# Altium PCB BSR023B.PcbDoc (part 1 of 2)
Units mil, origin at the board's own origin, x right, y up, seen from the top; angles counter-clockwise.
Board outline 3000 x 3000 mil, 4 copper layers (Top Layer, MidLayer 1, Mid Layer 2, Bottom Layer), stack 60.8 mil thick; 95 components, 24 nets, 183 pads, 215 vias.
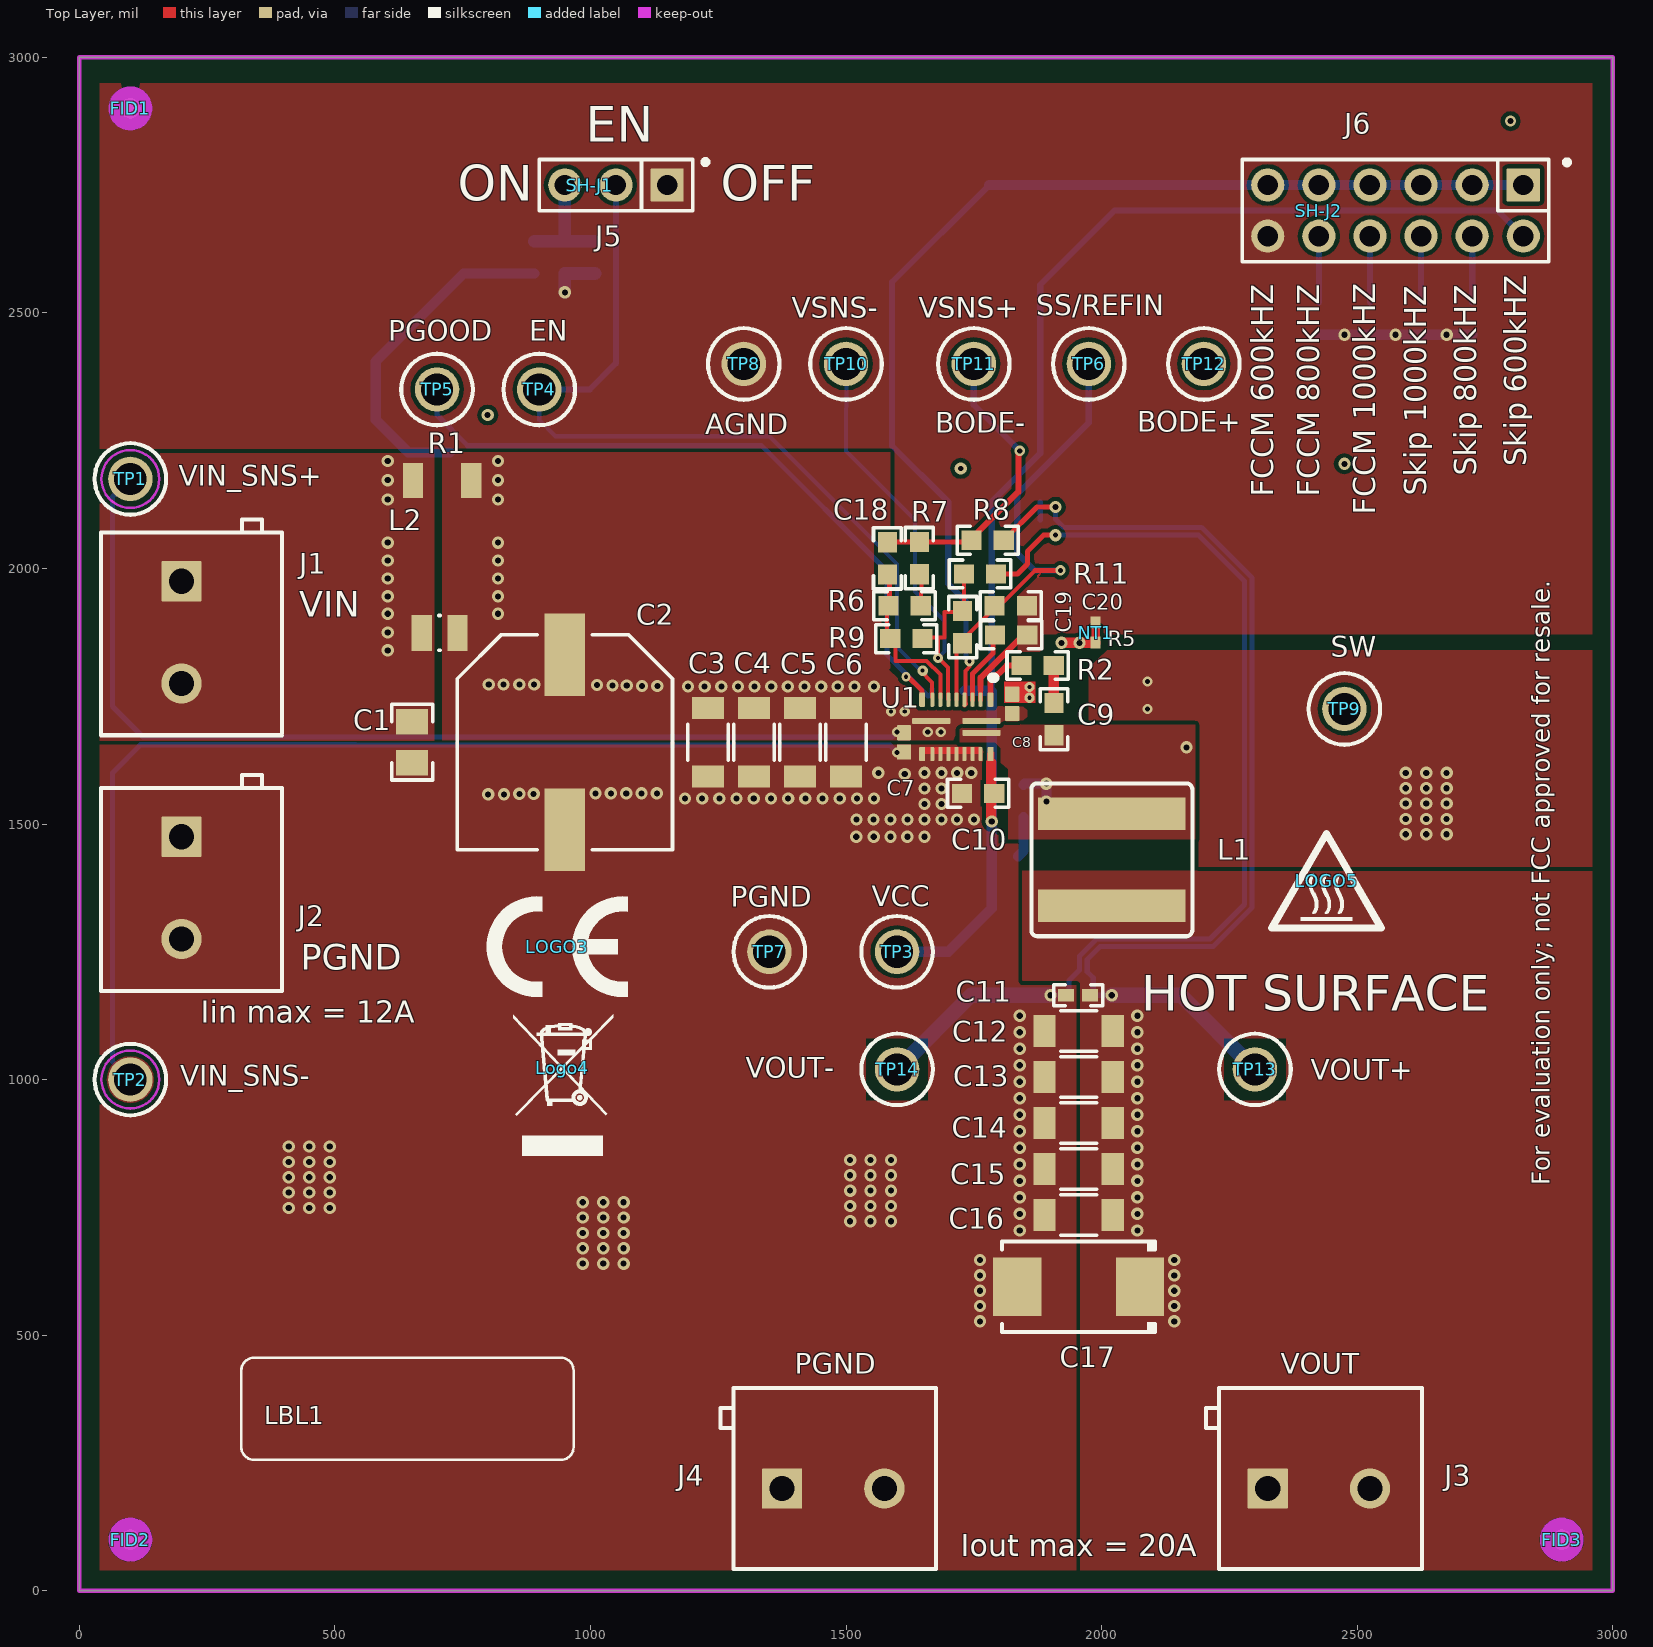
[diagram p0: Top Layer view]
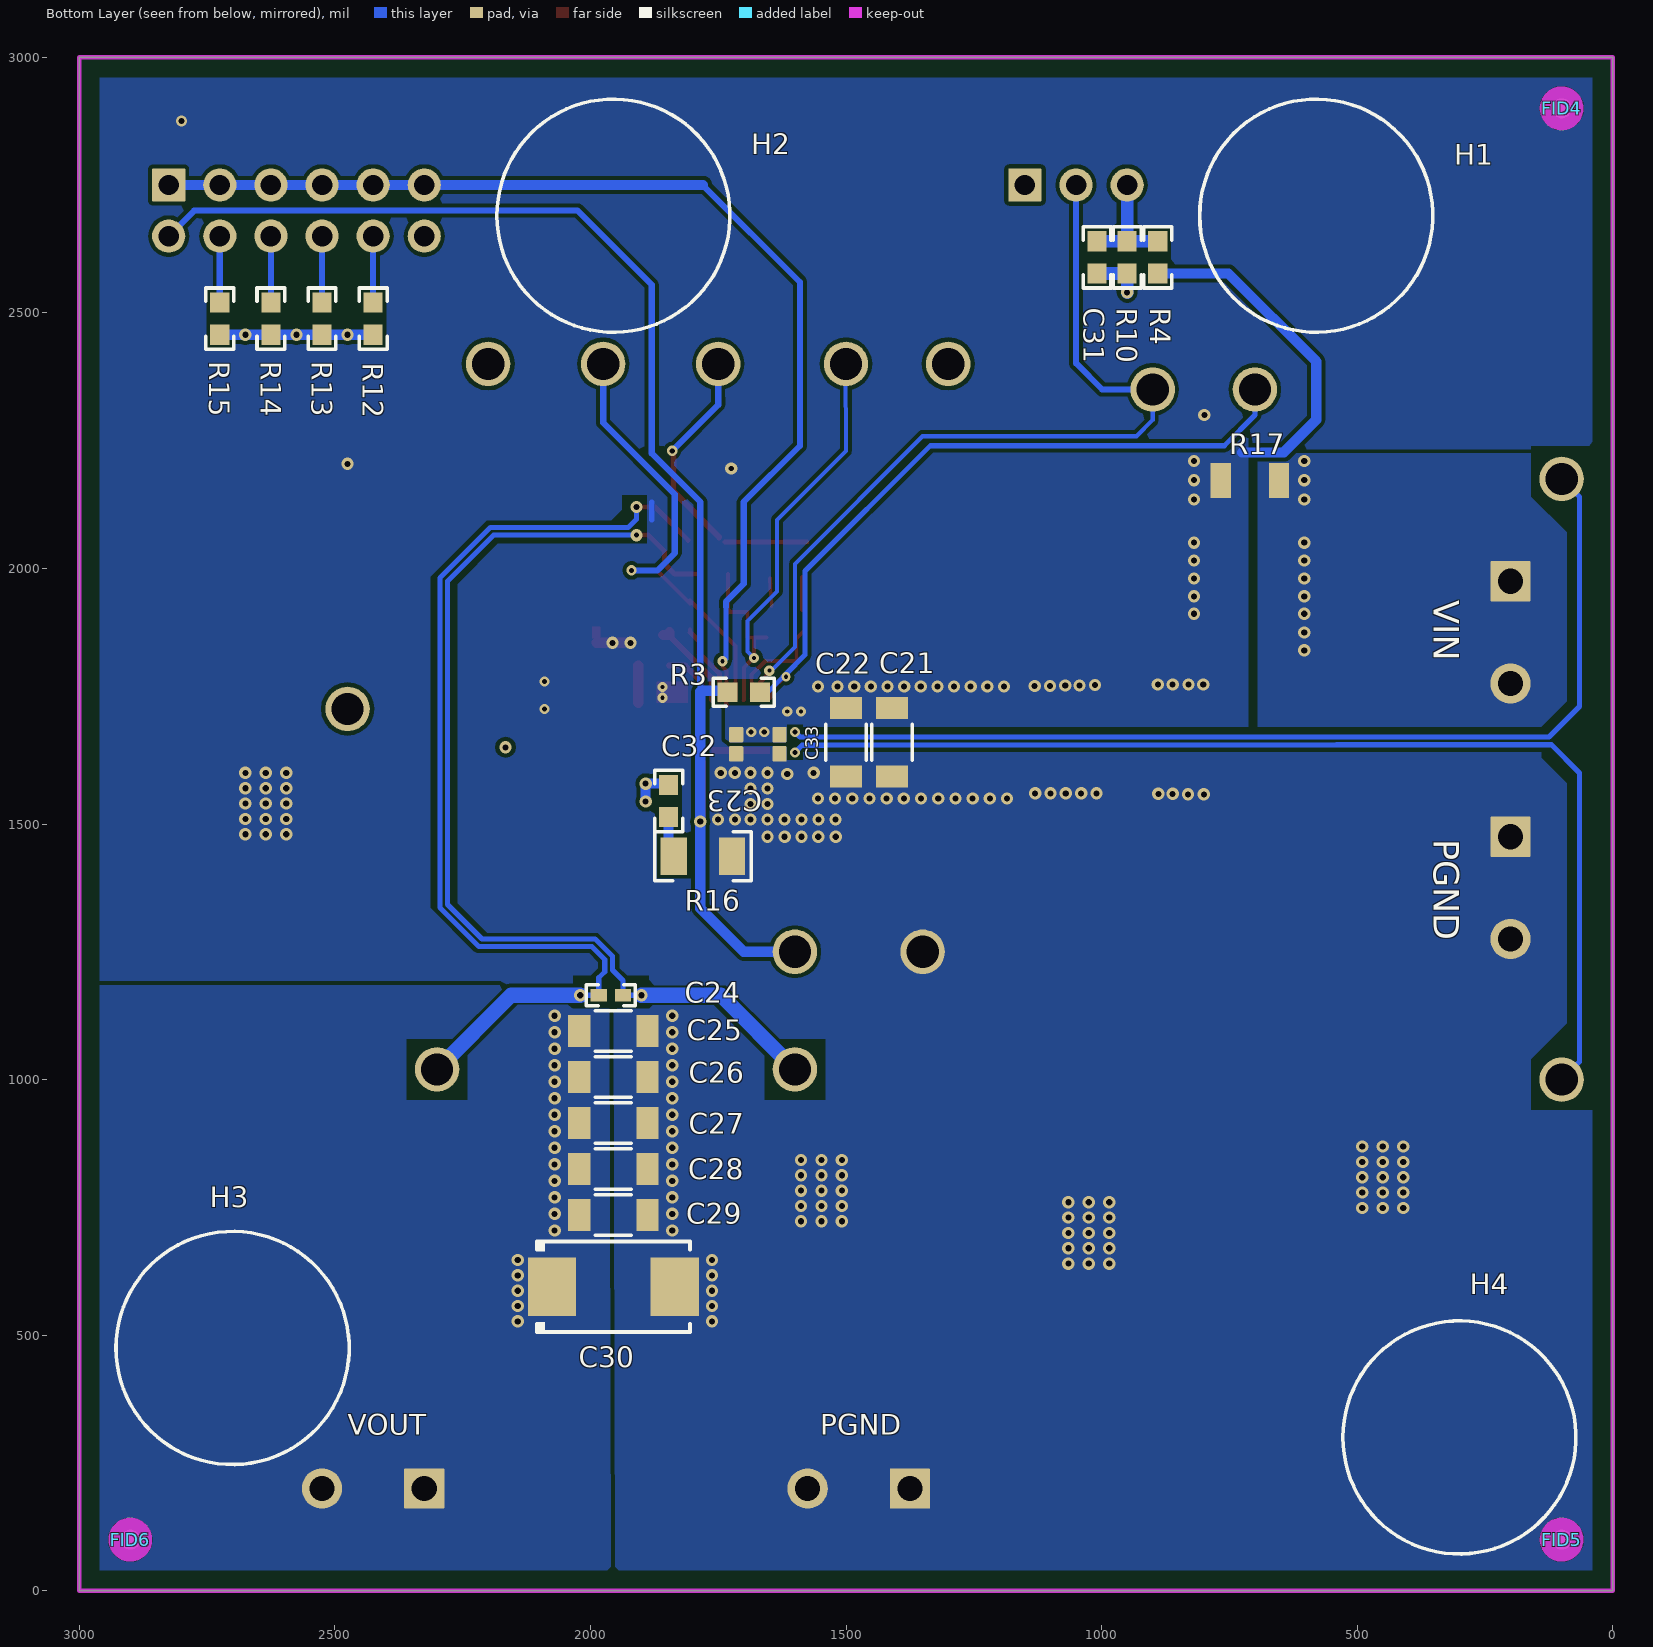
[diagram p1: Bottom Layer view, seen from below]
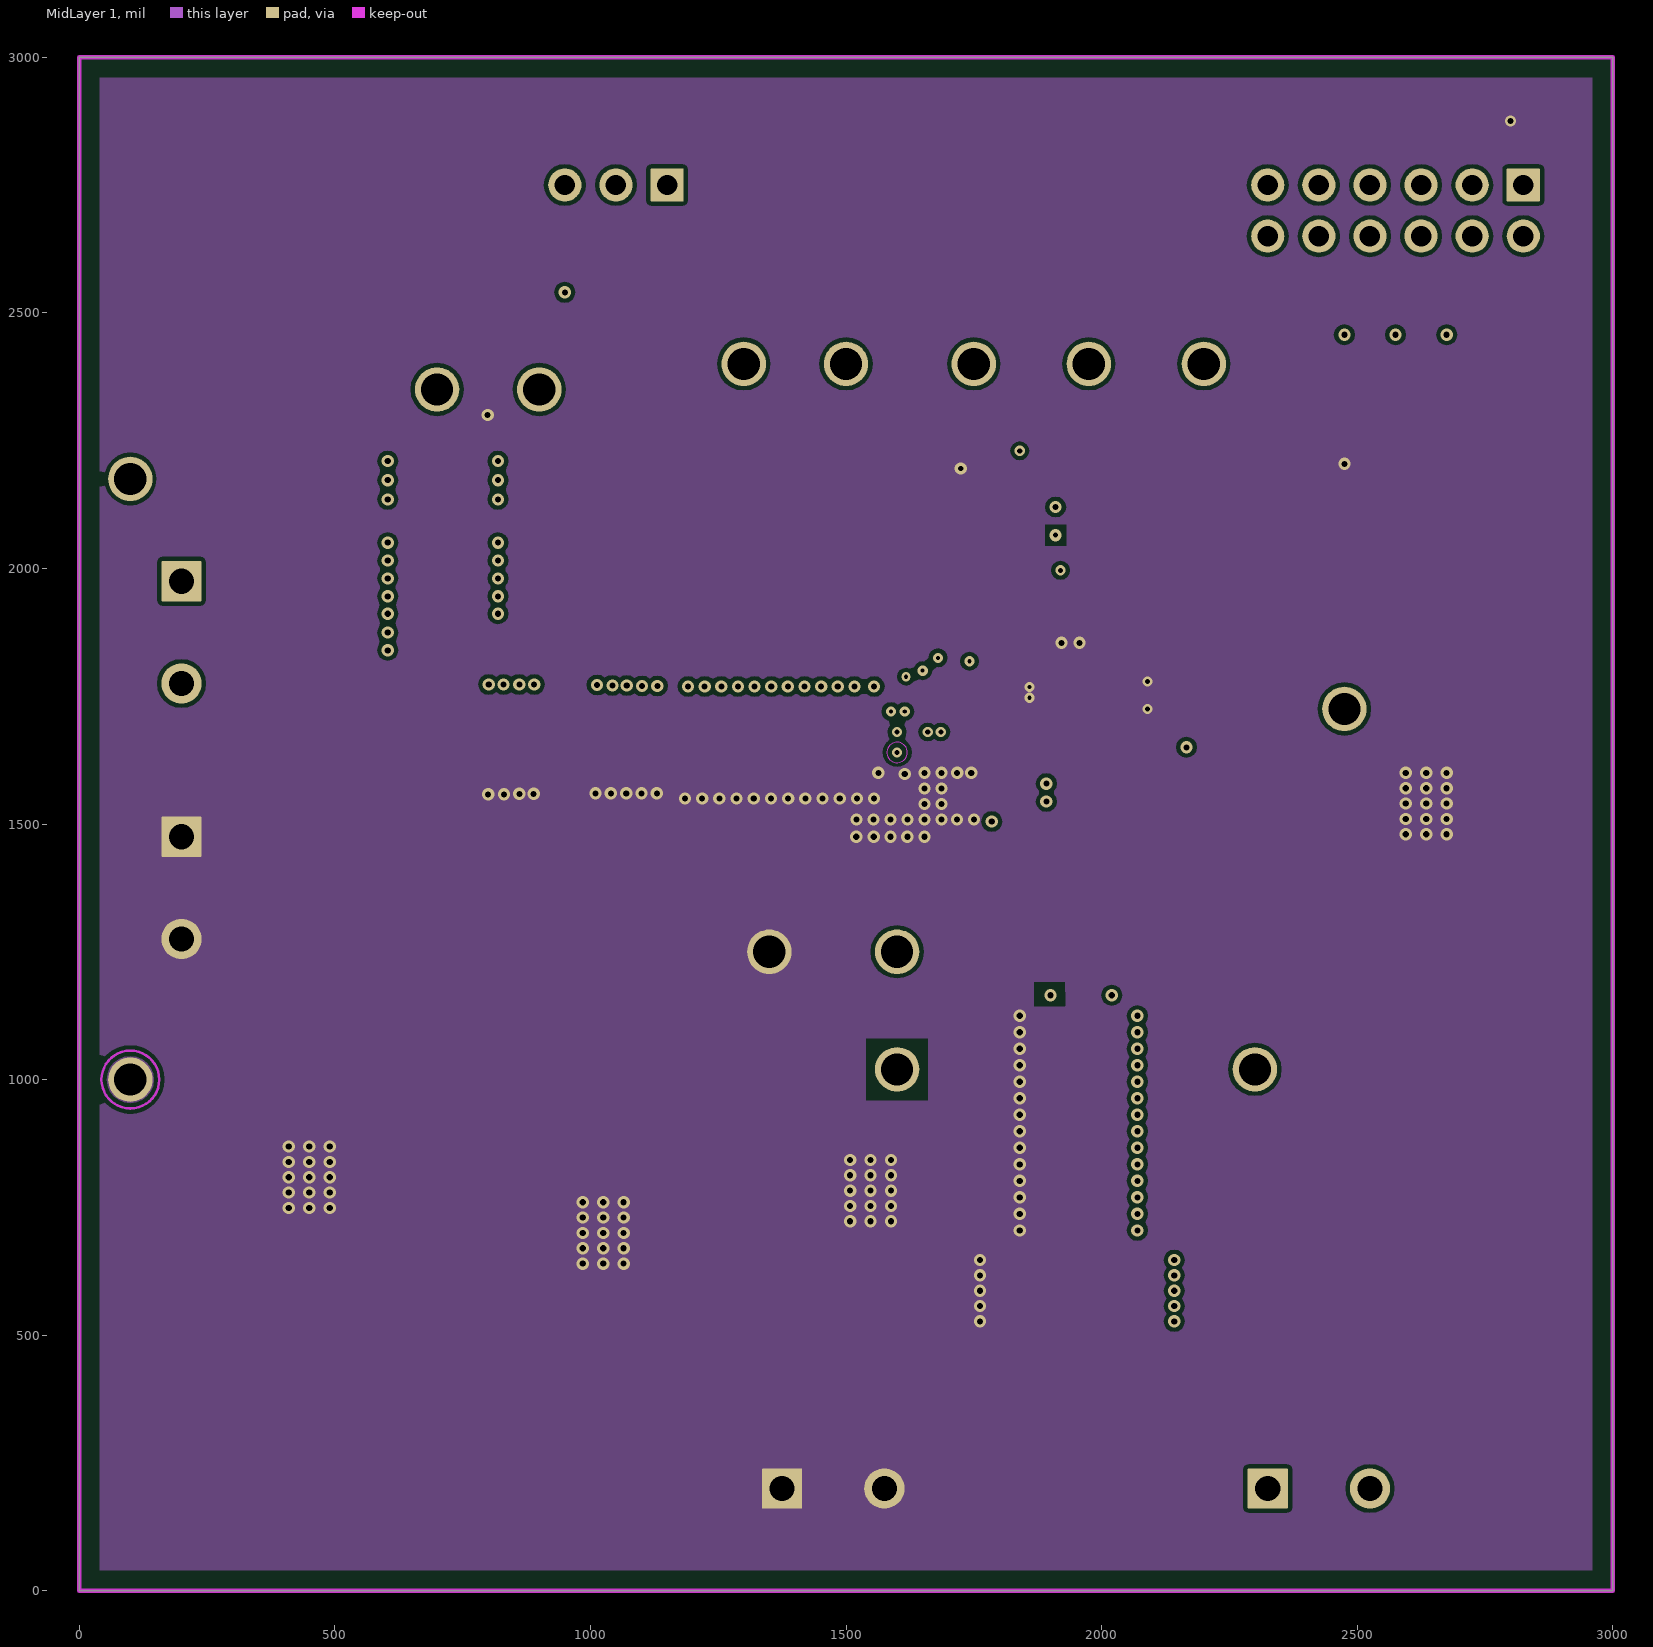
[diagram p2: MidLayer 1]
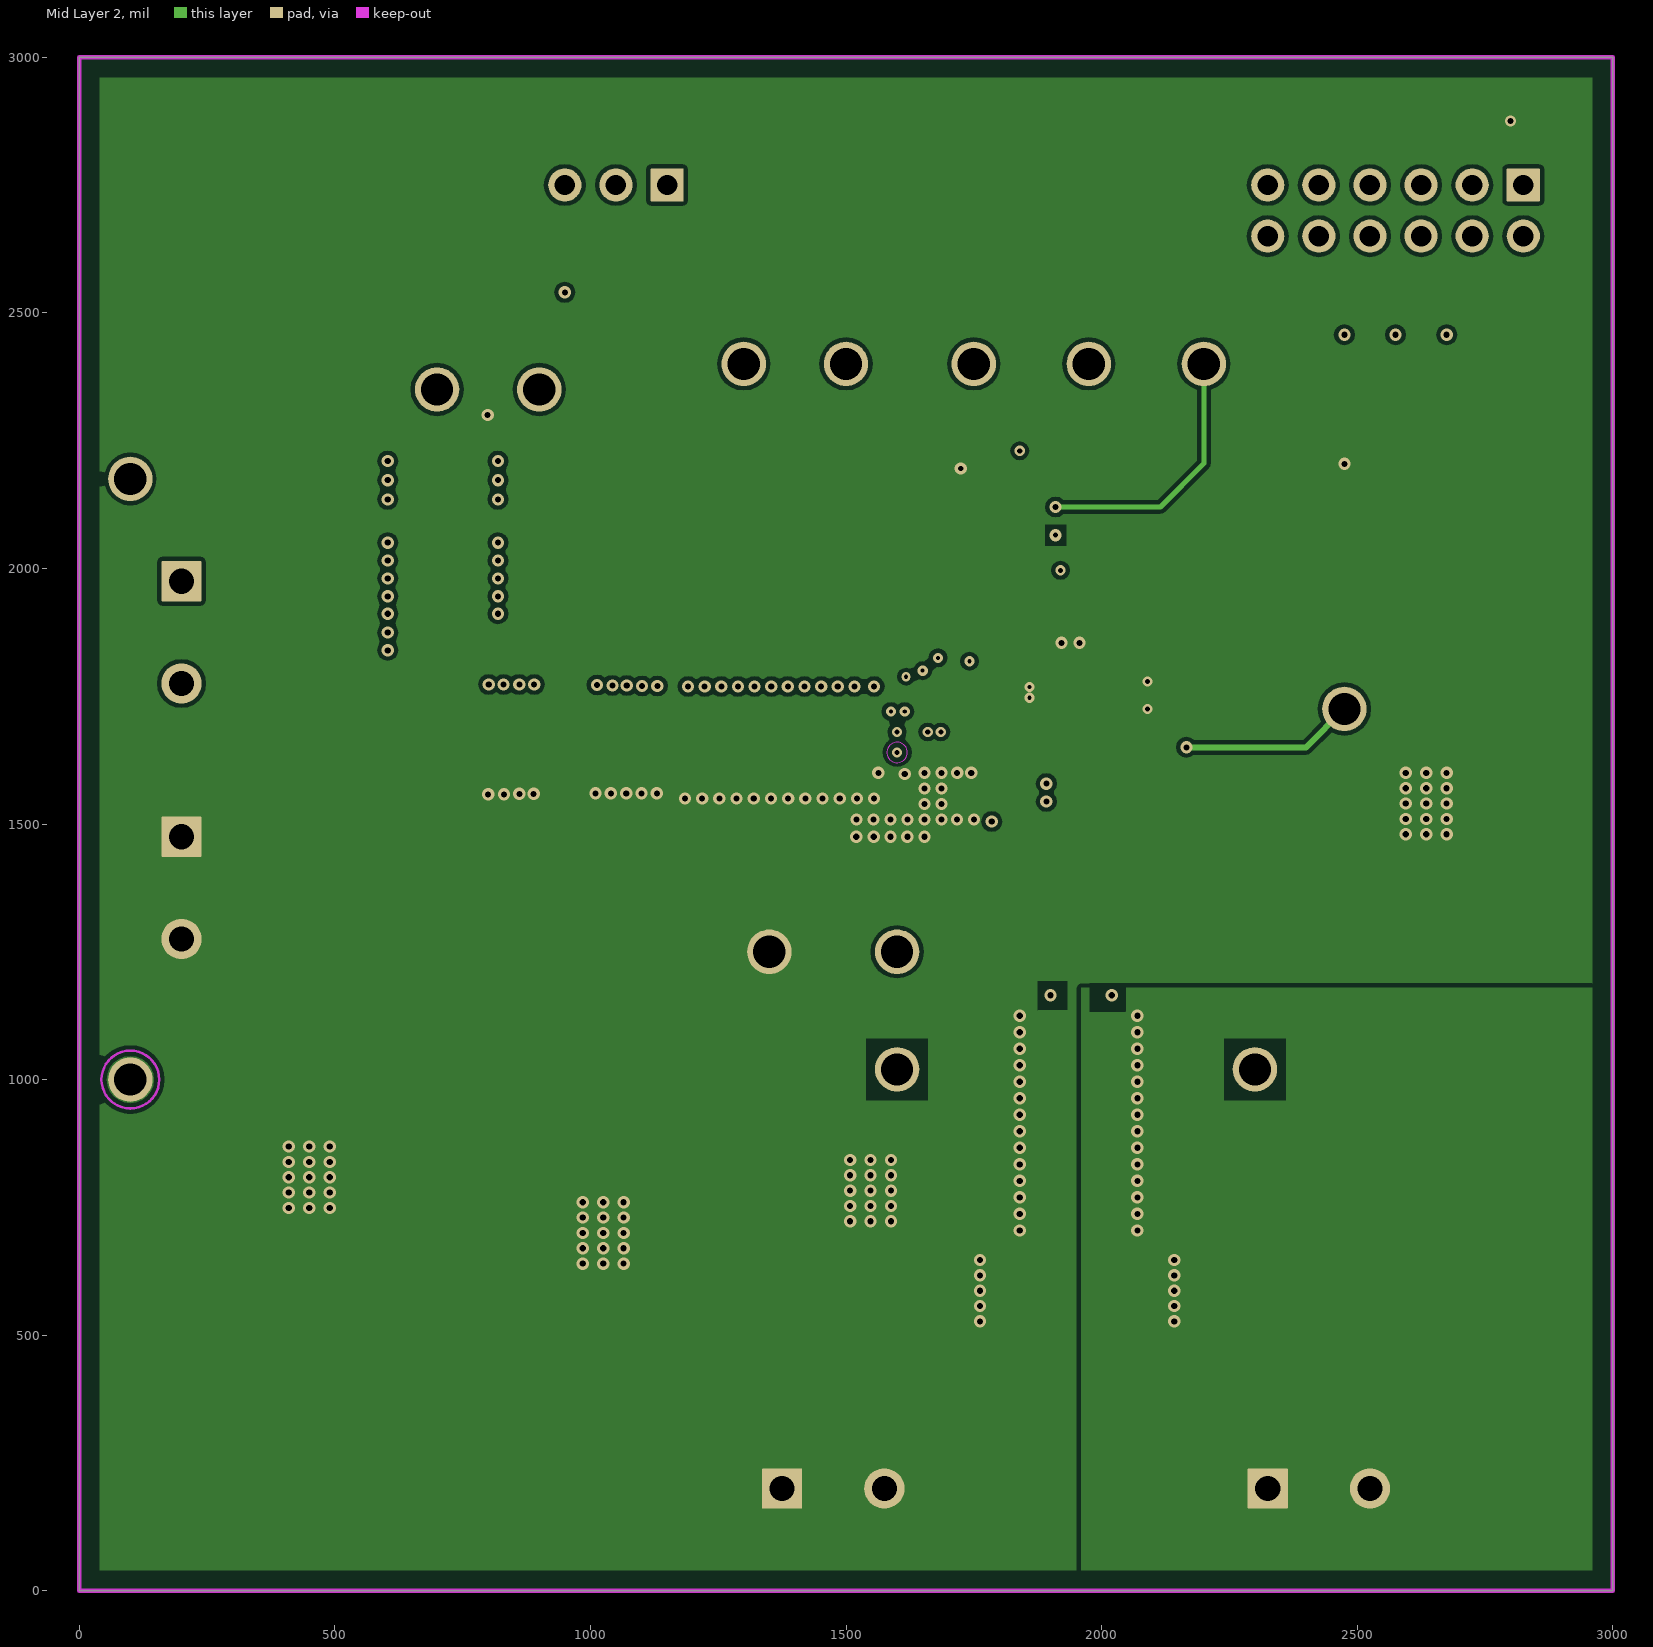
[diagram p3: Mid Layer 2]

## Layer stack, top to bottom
Top Solder: solder mask 0.4, Solder Resist, Dk 3.5
Top Layer: signal copper 2.8
Dielectric1: prepreg 9.3, FR-4 High TG, Dk 4.2
MidLayer 1: signal copper 2.8
Dielectric 2: core 31, FR-4 High TG, Dk 4.2
Mid Layer 2: signal copper 2.8
Dielectric 3: prepreg 9.3, FR-4 High TG, Dk 4.2
Bottom Layer: signal copper 2.8
Bottom Solder: solder mask 0.4, Solder Resist, Dk 3.5

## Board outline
0,0 0,3000 3000,3000 3000,0

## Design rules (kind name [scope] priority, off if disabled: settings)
AcuteAngle [All] p1: minimum=4.50000000000000E+0001 checktracksonly=FALSE
AssemblyTestPointUsage [All] p1: valid=2
BoardOutlineClearance BoardOutlineClearance_MountingHoles [OnCopper and InComponentClass('Mounting Holes')] p1: gap=40 ignorepadtopadclearanceinfootprint=FALSE
BoardOutlineClearance BoardOutlineClearance_Poly [OnCopper and InPoly] p2: gap=25 ignorepadtopadclearanceinfootprint=FALSE
BoardOutlineClearance [OnCopper and Not InComponentClass('Logo') and not InComponentClass('FiducialMark') and not InRegion(1000,500,4000,800)] p3: gap=40 ignorepadtopadclearanceinfootprint=FALSE
Clearance Clearance_Fiducial [(InComponentClass('FiducialMark') AND IsArc)] p1: gap=0 ignorepadtopadclearanceinfootprint=TRUE
Clearance Clearance_Keepouts [((IsTrack Or IsArc) And Not InPoly) And IsFree and IsKeepOut vs ((IsTrack Or IsArc) And Not InPoly) And IsFree and IsKeepOut] p2: gap=0 ignorepadtopadclearanceinfootprint=FALSE
Clearance Clearance_Poly [InPolygon] p3: gap=8 ignorepadtopadclearanceinfootprint=FALSE except(0: Arc-Hole Track-Hole SMDPad-Hole THPad-Hole Via-Hole Fill-Hole Poly-Hole Region-Hole Text-Hole)
Clearance [All] p4: gap=5 ignorepadtopadclearanceinfootprint=TRUE
ComponentClearance ComponentClearance_U1 [InComponent('U1')] p1: gap=3 collisioncheckmode=3 verticalgap=3 showdistances=FALSE
ComponentClearance ComponentClearance_MountingHoles_FiducialMarks [InComponentClass('Mounting Holes') vs InComponentClass('FiducialMark')] p2: gap=50 collisioncheckmode=3 verticalgap=8 showdistances=TRUE
ComponentClearance ComponentClearance_Shunt [InComponentClass('Header') vs InComponentClass('Shunt')] p3: gap=0 collisioncheckmode=3 verticalgap=0 showdistances=FALSE
ComponentClearance ComponentClearance_Logo [InComponentClass('Logo')] p4: gap=50 collisioncheckmode=3 verticalgap=10 showdistances=FALSE
ComponentClearance ComponentClearance_ScrewToNut [(HasFootprint('NY PMS 440 0025 PH')) vs (HasFootprint('Keystone_1902C'))] p5: gap=5 collisioncheckmode=3 verticalgap=10 showdistances=FALSE
ComponentClearance ComponentClearance_MountingHoles [InComponentClass('Mounting Holes')] p6: gap=250 collisioncheckmode=3 verticalgap=100000 showdistances=FALSE
ComponentClearance ComponentClearance_SmallPassives [HasFootprint('0201*') or HasFootprint('0402*') or HasFootprint('0508') or HasFootprint('0603*') or HasFootprint('0612') or HasFootprint('0805*') or HasFootprint('0815*') or HasFootprint('0830*') or HasFootprint('1206*') or HasFootprint('1210*') or HasFootprint('1808*') or HasFootprint('1812*') or HasFootprint('1825*') or HasFootprint('2010*') or HasFootprint('2220*') or HasFootprint('2225*') or HasFootprint('2512*') or HasFootprint('2728*') or HasFootprint('3518*') vs HasFootprint('0201*') or HasFootprint('0402*') or HasFootprint('0508') or HasFootprint('0603*') or HasFootprint('0612') or HasFootprint('0805*') or HasFootprint('0815*') or HasFootprint('0830*') or HasFootprint('1206*') or HasFootprint('1210*') or HasFootprint('1808*') or HasFootprint('1812*') or HasFootprint('1825*') or HasFootprint('2010*') or HasFootprint('2220*') or HasFootprint('2225*') or HasFootprint('2512*') or HasFootprint('2728*') or HasFootprint('3518*')] p7: gap=5 collisioncheckmode=3 verticalgap=5 showdistances=FALSE
ComponentClearance ComponentClearance_THtoSMT [IsThruComponent vs IsSMTComponent] p8: gap=10 collisioncheckmode=3 verticalgap=10 showdistances=FALSE
ComponentClearance ComponentClearance_THtoTH [IsThruComponent vs IsThruComponent] p9: gap=10 collisioncheckmode=3 verticalgap=10 showdistances=FALSE
ComponentClearance [All] p10: gap=8 collisioncheckmode=3 verticalgap=8 showdistances=FALSE
DiffPairsRouting [All] p1: maxlimit=100 minlimit=10 mostfreqgap=10 toplayer_minwidth=15 toplayer_maxwidth=15 toplayer_prefwidth=15 midlayer1_minwidth=15 midlayer1_maxwidth=15 midlayer1_prefwidth=15 midlayer2_minwidth=15 midlayer2_maxwidth=15 midlayer2_prefwidth=15 bottomlayer_minwidth=15 bottomlayer_maxwidth=15 bottomlayer_prefwidth=15 maxuncoupledlength=1000
FabricationTestPointUsage TestPointUsage [All] p1: valid=2 allowmultiple=FALSE
FabricationTestpoint Testpoint [All] p1: side=3 testpointundercomponent=TRUE minsize=40 maxsize=100 preferedsize=60 minholesize=0 maxholesize=40 preferedholesize=32 testpointgrid=1 allowsidetop=TRUE allowsidebottom=TRUE usegrid=TRUE gridtolerance=0.01
FanoutControl Fanout_LCC [IsLCC] p1: bgadir=Out bgaviamode=Centered fanoutstyle=Auto fanoutdirection=Alternating viagrid=1 // Fanout_LCC (Default Rule)
FanoutControl Fanout_BGA [IsBGA] p2: bgadir=Out bgaviamode=Centered fanoutstyle=Auto fanoutdirection=Alternating viagrid=1 // Fanout_BGA (Default Rule)
FanoutControl Fanout_Default [All] p4: bgadir=Out bgaviamode=Centered fanoutstyle=Auto fanoutdirection=Alternating viagrid=1 // Fanout_Default (Default Rule)
FanoutControl Fanout_Small [(CompPinCount < 5)] p5: bgadir=Out bgaviamode=Centered fanoutstyle=Auto fanoutdirection=OutThenIn viagrid=1 // Fanout_Small (Default Rule)
HoleSize [All] p1: absolutevalues=TRUE maxlimit=251 minlimit=7.87 maxpercent=80.000 minpercent=20.000
MinimumAnnularRing MinimumAnnularRing_ThermalPadVias [IsVia and InAnyComponent] p1: minimumring=5.91
MinimumAnnularRing [All] p2: minimumring=5
MinimumSolderMaskSliver MinimumSolderMaskSliver_Logo [InComponentClass('Logo') vs InComponentClass('Logo')] p1: minsoldermaskwidth=0.7
MinimumSolderMaskSliver [All] p2: minsoldermaskwidth=2
PlaneConnect [All] p1: planeconnectstyle=Relief reliefexpansion=10 reliefentries=4 reliefconductorwidth=10 reliefairgap=10
PolygonConnect [All] p1: connectstyle=Direct reliefconductorwidth=10 reliefentries=4 polygonreliefangle="90 Angle" airgapwidth=10
RoutingVias ThermalPadVias [IsVia and InAnyComponent] p1: holewidth=7.87 width=19.68 viastyle="Through Hole" minholewidth=7.87 minwidth=19.68 maxholewidth=12.99 maxwidth=23.62
RoutingVias [All] p2: holewidth=16 width=34 viastyle="Through Hole" minholewidth=7.87 minwidth=7 maxholewidth=40 maxwidth=65
SilkToBoardRegionClearance [Not ((IsComment or IsDesignator) And (Hide <> 'False')) and not InRegion(1000,500,4000,800)] p1:
SilkToSilkClearance SilkToSilkClearance_Pb-FreeLogo [(HasFootprint('Pb-Free_Overlay_Medium') OR HasFootprint('Pb-Free_Overlay_Small')) vs (HasFootprint('Pb-Free_Overlay_Medium') OR HasFootprint('Pb-Free_Overlay_Small'))] p1: silktosilkclearance=0
SilkToSilkClearance [All] p2: silktosilkclearance=1
SilkToSolderMaskClearance SilkToComponentPadClearance [IsPad and InAnycomponent] p1: minsilkscreentomaskgap=5 clearancetoexposedcopper=TRUE
SilkToSolderMaskClearance "Silk to Solder Mask Opening" [All] p2: minsilkscreentomaskgap=4 clearancetoexposedcopper=FALSE
SolderMaskExpansion [All] p1: expansion=1.97
Width [All] p1: maxlimit=100 minlimit=6 preferedwidth=10 checkconnectedcopper=TRUE
15 further rules are at their usual default settings.

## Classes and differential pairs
component class AssemblyNote: ZZ1 ZZ2 ZZ3 ZZ4
component class Shunt: SH-J1 SH-J2
component class BSR023B_Hardware: FID1 FID2 FID3 FID4 FID5 FID6 H1 H2 H3 H4 LBL1 Logo2 LOGO3 Logo4 LOGO5 Logo? LOGO? SH-J1 SH-J2 ZZ1 ZZ2 ZZ3 ZZ4
component class FiducialMark: FID1 FID2 FID3 FID4 FID5 FID6
component class Label: LBL1
component class Header: J5 J6
component class BSR023B: C1 C2 C3 C4 C5 C6 C7 C8 C9 C10 C11 C12 C13 C14 C15 C16 C17 C18 C19 C20 C21 C22 C23 C24 C25 C26 C27 C28 C29 C30 C31 C32 C33 C41 C42 J1 J2 J3 J4 J5 J6 L1 L2 NT1 PGND PGND2 PGND3 "PGND 1" "PGND 2" R1 R2 R3 R4 R5 R6 R7 R8 R9 R10 R11 R12 R13 R14 R15 R16 R17 TP1 TP2 TP3 TP4 TP5 TP6 TP7 TP8 TP9 TP10 TP11 TP12 TP13 TP14 U1 VOUT VOUT2 Vout-

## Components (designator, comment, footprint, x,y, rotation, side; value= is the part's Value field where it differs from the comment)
C1 "GRM21BZ71E106KE15L" 0805_HV 651.23,1660 r270 top value=10uF
C2 "EEE-FC1E331P" SM_RADIAL_G 950,1660 r270 top value=330uF
C3 "GRM31CC81E226ME11L" 1206_190 1230,1660 r270 top value=22uF
C4 "GRM31CC81E226ME11L" 1206_190 1320,1660 r270 top value=22uF
C5 "GRM31CC81E226ME11L" 1206_190 1410,1660 r270 top value=22uF
C6 "GRM31CC81E226ME11L" 1206_190 1500,1660 r270 top value=22uF
C7 "1uF" FP-GRM155C81E105KE11D_0402-IPC_A 1613.44,1659.71 r270 top
C8 "1uF" FP-GRM155C81E105KE11D_0402-IPC_A 1825,1735 r90 top
C9 "CGA3E2X7R1H104K080AA" 0603 1907,1705 r90 top value=0.1uF
C10 "GRM188R71A225KE15D" 0603 1758.51,1560 r180 top value=2.2uF
C11 "GRM155R70J104KA01D" 0402 1954,1165 r180 top value=0.1uF
C12 "GRM31CC80J476KE18L" 1206_180 1955,1095 r180 top value=47uF
C13 "GRM31CC80J476KE18L" 1206_180 1955,1005 r180 top value=47uF
C14 "GRM31CC80J476KE18L" 1206_180 1955,915 r180 top value=47uF
C15 "GRM31CC80J476KE18L" 1206_180 1955,825 r180 top value=47uF
C16 "GRM31CC80J476KE18L" 1206_180 1955,735 r180 top value=47uF
C17 "6TPF470MAH" 7343-40 1955,595 r180 top value=470uF
C18 "C0603X222K5RACTU" 0603 1581.03,2019.76 r270 top value=2200pF
C19 "C1608X7R1C224K080AC" 0603 1728.26,1885 r90 top value=0.22uF
C20 "C0603C223K4RACTU" 0603 1822.24,1927 r0 top value=0.022uF
C21 "GRM31CC81E226ME11L" 1206_190 1410,1660 r270 bottom value=22uF
C22 "GRM31CC81E226ME11L" 1206_190 1500,1660 r270 bottom value=22uF
C23 "CL10C102JB8NNNC" 0603 1847,1545 r270 bottom value=1000pF
C24 "GRM155R70J104KA01D" 0402 1960,1165 r180 bottom value=0.1uF
C25 "GRM31CC80J476KE18L" 1206_180 1955,1095 r180 bottom value=47uF
C26 "GRM31CC80J476KE18L" 1206_180 1955,1005 r180 bottom value=47uF
C27 "GRM31CC80J476KE18L" 1206_180 1955,915 r180 bottom value=47uF
C28 "GRM31CC80J476KE18L" 1206_180 1955,825 r180 bottom value=47uF
C29 "GRM31CC80J476KE18L" 1206_180 1955,735 r180 bottom value=47uF
C30 "6TPF470MAH" 7343-40 1955,595 r180 bottom value=470uF
C31 "885012206040" 0603 1008.9,2608.5 r270 bottom value=0.01uF
C32 "1uF" FP-GRM155C81E105KE11D_0402-IPC_A 1715,1656 r270 bottom
C33 "1uF" FP-GRM155C81E105KE11D_0402-IPC_A 1630,1656 r270 bottom
FID1 "Fiducial" Fiducial10-20 100,2900 r0 top
FID2 "Fiducial" Fiducial10-20 100,100 r0 top
FID3 "Fiducial" Fiducial10-20 2900,100 r0 top
FID4 "Fiducial" Fiducial10-20 100,2900 r180 bottom
FID5 "Fiducial" Fiducial10-20 100,100 r180 bottom
FID6 "Fiducial" Fiducial10-20 2900,100 r180 bottom
H1 "SJ-5303 (CLEAR)" Bumpon_SJ5003Transparent 580,2690 r90 bottom
H2 "SJ-5303 (CLEAR)" Bumpon_SJ5003Transparent 1955,2690 r90 bottom
H3 "SJ-5303 (CLEAR)" Bumpon_SJ5003Transparent 2700,475 r90 bottom
H4 "SJ-5303 (CLEAR)" Bumpon_SJ5003Transparent 300,300 r90 bottom
J1 "ED120/2DS" On-Shore_ED120_2DS 200,1875 r270 top
J2 "ED120/2DS" On-Shore_ED120_2DS 200,1375 r270 top
J3 "ED120/2DS" On-Shore_ED120_2DS 2425,200 r0 top
J4 "ED120/2DS" On-Shore_ED120_2DS 1475,200 r0 top
J5 "" Samtec_HTSW-103-07-G-S 1050,2750 r180 top
J6 "TSW-106-07-G-D" TSW-106-07-G-D 2575,2700 r180 top
L1 "XAL7070-551MEB" XAL7070 2020,1430 r270 top value=550nH
L2 "L_Filt" 0805CS 705,1873.91 r0 top value=47nH
LBL1 "THT-14-423-10" Label_650x200 642.13,356 r0 top
Logo2 "FCC disclaimer" FCC_disclaimer 4416,4871 r90 top
LOGO3 "CE Mark" CE_Mark_5mm 935,1260 r0 top
Logo4 "WEEE logo" WEEE_Minimum 945,1022.98 r0 top
LOGO5 "CAUTION HOT SURFACE" IEC_HotSurface_Small 2440,1389.36 r0 top
NT1 "Net-Tie" NetTie_0402 1988.34,1874.38 r270 top net-tie
R1 "5108" 5108 710,2172 r0 top value=0
R2 "RMCF0603ZT0R00" 0603 1875,1810 r0 top value=0
R3 "CRCW060330K1FKEA" 0603 1700.07,1757.8 r180 bottom value=30.1k
R4 "RT0603BRD0720KL" 0603 890.13,2608.5 r270 bottom value=20.0k
R5 "CRCW06036K04FKEA" 0603 1823.04,1870 r180 top value=6.04k
R6 "CRCW060318K7FKEA" 0603 1614.64,1927 r0 top value=18.7k
R7 "RMCF0603ZT0R00" 0603 1643.58,2020 r90 top value=0
R8 "CRCW060310R0FKEA" 0603 1777.21,2055 r180 top value=10.0
R9 "CRCW060310K0FKEA" 0603 1617.94,1862.57 r0 top value=10.0k
R10 "CRCW060310K0FKEA" 0603 950,2608.5 r90 bottom value=10.0k
R11 "RMCF0603ZT0R00" 0603 1762.26,1989.2 r180 top value=0
R12 "CRCW060330K1FKEA" 0603 2425,2488.5 r90 bottom value=30.1k
R13 "RC0603FR-0760K4L" 0603 2525,2488.5 r90 bottom value=60.4k
R14 "RC0603FR-07121KL" 0603 2625,2488.5 r90 bottom value=121k
R15 "CRCW0603243KFKEA" 0603 2725,2488.5 r270 bottom value=243k
R16 "CRM1206-JW-2R2ELF" 1206 1780,1437 r0 bottom value=2.2
R17 "5108" 5108 710,2172 r0 bottom value=0
SH-J1 "SNT-100-BK-G" SNT-100-BK-G 998.8,2750 r180 top value=1x2
SH-J2 "SNT-100-BK-G" SNT-100-BK-G 2425,2700 r90 top value=1x2
TP1 "VIN_SNS+" Keystone5010 100,2175 r90 top
TP2 "VIN_SNS-" Keystone5011 100,1000 r90 top
TP3 "VCC" Keystone5010 1600,1250 r90 top
TP4 "EN" Keystone5009 900,2350 r0 top
TP5 "PGOOD" Keystone5009 700,2350 r180 top
TP6 "SS/REFIN" Keystone5009 1975,2400 r180 top
TP7 "PGND" Keystone5011 1350,1250 r90 top
TP8 "AGND" Keystone5011 1300,2400 r90 top
TP9 "SW" Keystone5008 2475,1725 r90 top
TP10 "VSNS-" Keystone5013 1500,2400 r90 top
TP11 "BODE-" Keystone5013 1750,2400 r90 top
TP12 "BODE+" Keystone5013 2200,2400 r90 top
TP13 "VOUT+" Keystone5010 2300,1020 r90 top
TP14 "VOUT-" Keystone5011 1600,1020 r90 top
U1 "TPS54JB00" RWW0021A 1716,1690 r270 top
ZZ1 "This Assembly Note is for PCB labels only" AssemblyNoteLabel 635,6660 r0 top
ZZ2 "These assemblies are ESD sensitive, ESD precautions shall be observed." AssemblyNote 632,6468 r0 top
ZZ3 "These assemblies must be clean and free from flux and all contaminants. Use of no clean flux is not acceptable." AssemblyNote 637,6305 r0 top
ZZ4 "These assemblies must comply with workmanship standards IPC-A-610 Class 2, unless otherwise specified." AssemblyNote 637,6113 r0 top

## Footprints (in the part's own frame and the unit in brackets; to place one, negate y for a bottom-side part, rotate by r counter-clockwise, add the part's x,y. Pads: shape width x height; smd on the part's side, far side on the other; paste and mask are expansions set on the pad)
0402 [mm] "0402 from SM-752 data"
  rect 0.8x0.6 smd: 1(-0.6,0) 2(0.6,0)
  silkscreen extent -1.22,-0.52 1.22,0.52, body extent -0.55,-0.3 0.55,0.3, height 0.6
0603 [mm] "0603 from SM-752 data"
  rect 1x0.95 smd: 1(-0.8,0) 2(0.8,0)
  silkscreen extent -1.52,-0.69 1.52,0.69, body extent -0.87,-0.47 0.87,0.47, height 1
0805_HV [mil] "0805 with 30mil clearance between pads"
  rect 50x63 smd: 1(-40,0) 2(40,0)
  silkscreen extent -74,-40 74,40, body extent -43,-29 43,29, height 57
0805CS [mil] "Coilcraft Chip Inductors - 0805CS Series (2012)"
  rect 40x70 smd: 1(-35,0) 2(35,0)
  silkscreen extent -2,-34 2,34, body extent -45,-34 45,34, height 60
1206 [mm] "1206 from SM-752 data"
  rect 1.3x1.85 smd: 1(-1.45,0) 2(1.45,0)
  silkscreen extent -2.4,-1.21 2.4,1.21, body extent -1.7,-0.9 1.7,0.9, height 1.35
1206_180 [mm] "1206_180"
  rect 1.1x1.6 smd: 1(-1.7,0) 2(1.7,0)
  silkscreen extent -0.9,-1 0.9,1, body extent -1.75,-0.95 1.75,0.95, height 1.8
1206_190 [mm] "1206_190"
  rect 1.1x1.6 smd: 1(-1.7,0) 2(1.7,0)
  silkscreen extent -0.9,-1 0.9,1, body extent -1.75,-0.95 1.75,0.95, height 1.9
5108 [mm] "Keystone"
  rect 1.01x1.73 smd: 1(-1.445,0) 2(1.445,0)
  body extent -1.52,-0.85 1.52,0.85, height 0.71
7343-40 [mm] "Molded, 2-Leads, Body 7.3x4.3mm, Height 4mm"
  rect 2.4x2.9 smd: 1(-3.05,0) 2(3.05,0)
  silkscreen extent -3.8,-2.25 3.8,2.25, body extent -3.8,-2.25 3.8,2.25, height 4.01
AssemblyNote [mil] "Assembly Note"
AssemblyNoteLabel [mil] "Assembly Note for PCB Labels"
Bumpon_SJ5003Transparent [mil] "3M Hemispherical Bumpon transparent"
  round 1 on Mech4: 0(0,0)
  silkscreen extent -228,-228 228,228, body extent -219,-219 219,219, height 197
CE_Mark_5mm [mil] "Minimum text height for CE Mark"
  silkscreen extent -138,-98 138,98
FCC_disclaimer [mil]
Fiducial10-20 [mm]
  round 1 smd mask+0.5: 1(0,0)
  Top Layer keep-out circle w1.178: c0,0 r0.5
FP-GRM155C81E105KE11D_0402-IPC_A [mil]
  rrect14% 29.91x28.04 smd paste+0 mask+0: 1(-18.75,0) 2(18.75,0)
  body extent -42,-22 42,22, height 10
IEC_HotSurface_Small [mil]
  silkscreen extent -107,-93 107,92
Keystone5008 [mil] "Keystone Compact loops"
  round 87 hole 63: 1(0,0)
  silkscreen extent -70,-70 70,70, body extent -63,-63 62,63, height 225
Keystone5009 [mil] "Keystone Compact loops"
  round 87 hole 63: 1(0,0)
  silkscreen extent -70,-70 70,70, body extent -63,-63 62,63, height 225
Keystone5010 [mil] "Keystone Multipurpose loops"
  round 87 hole 63: 1(0,0)
  silkscreen extent -70,-70 70,70, body extent -63,-63 63,62, height 319
Keystone5011 [mil] "Keystone Multipurpose loops"
  round 87 hole 63: 1(0,0)
  silkscreen extent -70,-70 70,70, body extent -63,-63 63,62, height 319
Keystone5013 [mil] "Keystone Multipurpose loops"
  round 87 hole 63: 1(0,0)
  silkscreen extent -70,-70 70,70, body extent -63,-63 63,62, height 319
Label_650x200 [mil] "Thermal Transfer Label"
  round 1 on Mech13: 0(0,0)
  silkscreen extent -325,-100 325,100, body extent -325,-100 325,100, height 1
NetTie_0402 [mm] "Net Tie 0402 size"
  rect 0.6x0.5 smd paste-0.5: 1(-0.5,0) 2(0.5,0)
  Top Layer region: -0.279,0.203 0.279,0.203 0.279,-0.203 -0.279,-0.203
On-Shore_ED120_2DS [mm] "ONSHORE"
  rrect5% 2x2 hole 1.25: 1(-2.54,0)
  round 2 hole 1.25: 2(2.54,0)
  silkscreen extent -5.6,-4 5.12,5, body extent -5.78,-4 5.08,5, height 13
RWW0021A [mm] "VQFN-HR-21"
  rrect33% 0.7x0.3 smd: 1(-1.35,1.7) 9(-1.35,-1.7) 11(1.35,-1.7) 19(1.35,1.7)
  rrect50% 0.7x0.2 smd: 2(-1.35,1.2) 3(-1.35,0.8) 4(-1.35,0.4) 5(-1.35,0) 6(-1.35,-0.4) 7(-1.35,-0.8) 8(-1.35,-1.2) 12(1.35,-1.2) 13(1.35,-0.8) 14(1.35,-0.4) 15(1.35,0) 16(1.35,0.4) 17(1.35,0.8) 18(1.35,1.2)
  rrect33% 0.3x1.9 smd paste-1: 10(-0.3,-1.25) 20(0.3,1.25) 21(-0.3,1.25)
  rrect33% 0.3x0.85 on Top Paste: 10A(-0.3,-0.725) 10B(-0.3,-1.775) 20A(0.3,1.775) 20B(0.3,0.725) 21A(-0.3,1.775) 21B(-0.3,0.725)
  Top Layer region: 1,-1.7 1.35,-1.7 1.35,1.2 1,1.2
  body extent -1.5,-2 1.5,2, height 1
Samtec_HTSW-103-07-G-S [mm] "Samtec 100mil, 1x3, 230 mil above insulator"
  rrect6% 1.65x1.65 hole 1.016: 1(-2.54,0)
  round 1.65 hole 1.016: 2(0,0) 3(2.54,0)
  silkscreen extent -4.57,-1.27 3.81,1.27, body extent -3.81,-1.27 3.81,1.27, height 8.38
SM_RADIAL_G [mm] "10 x 10.2mm:  Panasonic G"
  rect 4.1x2 smd: 1(-4.35,0) 2(4.35,0)
  silkscreen extent -5.35,-5.35 5.35,5.35, body extent -5.25,-5.25 5.25,5.25, height 10.5
SNT-100-BK-G [mil] "Samtec STEP model"
  round 1 on Mech3: 0(0,0)
  body extent -100,-50 100,50, height 344
TSW-106-07-G-D [mm] "Samtec 100mil, 2x6, 230 mil above insulator"
  rrect6% 1.65x1.65 hole 1.016: 1(-6.35,-1.27)
  round 1.65 hole 1.016: 2(-6.35,1.27) 3(-3.81,-1.27) 4(-3.81,1.27) 5(-1.27,-1.27) 6(-1.27,1.27) 7(1.27,-1.27) 8(1.27,1.27) 9(3.81,-1.27) 10(3.81,1.27) 11(6.35,-1.27) 12(6.35,1.27)
  silkscreen extent -8.65,-2.54 7.62,2.54, body extent -7.62,-2.54 7.62,2.54, height 8.38
WEEE_Minimum [mil] "WEEElie bin"
  silkscreen extent -95,-172 99,104
XAL7070 [mm] "COILCRAFT"
  rect 1.63x7.33 smd: 1(-2.285,0) 2(2.285,0)
  silkscreen extent -3.8,-4 3.8,4, body extent -3.8,-4 3.8,4, height 7

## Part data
C1: library part CMP-0008378-2, "CAP, CERM, 10 uF, 25 V, +/- 10%, X7R, 0805", Cap_Case=0805, Manufacturer=MuRata, Supplier Part Number 1=81-GRM21BZ71E106KE5L, TempCo=X7R, Tolerance_%=10%, Value1=Unknown, Value2=25V, ValueDisplayed=10uF
C2: library part CMP-0010657-1, "CAP, AL, 330 uF, 25 V, +/- 20%, 0.15 ohm, SMD", Cap_Case=G, Manufacturer=Panasonic, Supplier Part Number 1=PCE4007CT-ND, Tolerance_%=20%, Value1="0.15 ohm", Value2=25V, ValueDisplayed=330uF
C3 C4 C5 C6 C21 C22: library part CMP-0008928-3, "CAP, CERM, 22 uF, 25 V, +/- 20%, X6S, 1206_190", Cap_Case=1206, Manufacturer=MuRata, Supplier Part Number 1=81-GRM31CC81E226ME1L, TempCo=X6S, Tolerance_%=20%, Value1=Unknown, Value2=25V, ValueDisplayed=22uF
C7 C8 C32 C33: library part CMP-0086485-1, "CAP CER 1UF 25V X6S 0402", Manufacturer=Murata, PartNumber=GRM155C81E105KE11D, TempCo=22%, Tolerance_%=10%
C9: library part CMP-0007078-4, "CAP, CERM, 0.1 uF, 50 V, +/- 10%, X7R, AEC-Q200 Grade 1, 0603", Cap_Case=0603, Manufacturer=TDK, Supplier Part Number 1=445-5666-1-ND, TempCo=X7R, Tolerance_%=10%, Value1="0.0296 ohm", Value2=50V, ValueDisplayed=0.1uF
C10: library part CMP-0007370-4, "CAP, CERM, 2.2 uF, 10 V, +/- 10%, X7R, 0603", Cap_Case=0603, Manufacturer=MuRata, Supplier Part Number 1=490-4520-1-ND, TempCo=X7R, Tolerance_%=10%, Value1="0.009 ohm", Value2=10V, ValueDisplayed=2.2uF
C11 C24: library part CMP-0006623-2, "CAP, CERM, 0.1 uF, 6.3 V, +/- 10%, X7R, 0402", Cap_Case=0402, Manufacturer=MuRata, Supplier Part Number 1=GRM155R70J104KA01D-ND, TempCo=X7R, Tolerance_%=10%, Value1=Unknown, Value2=6.3V, ValueDisplayed=0.1uF
C12 C13 C14 C15 C16 C25 C26 C27 C28 C29: library part CMP-0008926-3, "CAP, CERM, 47 uF, 6.3 V, +/- 10%, X6S, 1206", Cap_Case=1206, Manufacturer=MuRata, Supplier Part Number 1=81-GRM31CC80J476KE8L, TempCo=X6S, Tolerance_%=10%, Value1=Unknown, Value2=6.3V, ValueDisplayed=47uF
C17 C30: library part CMP-0012642-3, "CAP, Tantalum Polymer, 470 uF, 6.3 V, +/- 20%, 0.01 ohm, 7343-40 SMD", Cap_Case=D4, Manufacturer=Panasonic, Supplier Part Number 1=P16636CT-ND, Tolerance_%=20%, Value1="0.01 ohm", Value2=6.3V, ValueDisplayed=470uF
C18: library part CMP-0006983-4, "CAP, CERM, 2200 pF, 50 V, +/- 10%, X7R, 0603", Cap_Case=0603, Manufacturer=Kemet, Supplier Part Number 1=399-5341-1-ND, TempCo=X7R, Tolerance_%=10%, Value1=Unknown, Value2=50V, ValueDisplayed=2200pF
C19: library part CMP-0007038-5, "CAP, CERM, 0.22 uF, 16 V, +/- 10%, X7R, 0603", Cap_Case=0603, Manufacturer=TDK, Supplier Part Number 1=445-1318-1-ND, TempCo=X7R, Tolerance_%=10%, Value1="0.0125 ohm", Value2=16V, ValueDisplayed=0.22uF
C20: library part CMP-0006900-4, "CAP, CERM, 0.022 uF, 16 V, +/- 10%, X7R, 0603", Cap_Case=0603, Manufacturer=Kemet, Supplier Part Number 1=399-1093-1-ND, TempCo=X7R, Tolerance_%=10%, Value1=Unknown, Value2=16V, ValueDisplayed=0.022uF
C23: library part CMP-0007114-5, "CAP, CERM, 1000 pF, 50 V, +/- 5%, X7R, 0603", Cap_Case=0603, Manufacturer="Samsung Electro-Mechanics", Supplier Part Number 1=1276-1091-1-ND, TempCo=X7R, Tolerance_%=5%, Value1=Unknown, Value2=50V, ValueDisplayed=1000pF
C31: library part CMP-0006828-4, "CAP, CERM, 0.01 uF, 16 V, +/- 10%, X7R, 0603", Cap_Case=0603, Manufacturer="Wurth Elektronik", Supplier Part Number 1=732-7959-1-ND, TempCo=X7R, Tolerance_%=10%, Value1=Unknown, Value2=16V, ValueDisplayed=0.01uF
FID1 FID2 FID3 FID4 FID5 FID6: library part CMP-0077181-1, "Fiducial mark.  There is nothing to buy or mount.", Manufacturer=N/A
H1 H2 H3 H4: library part CMP-0003620-1, "Bumpon, Hemisphere, 0.44 X 0.20, Clear", Manufacturer=3M, Supplier Part Number 1=SJ5303-7-ND
J1 J2 J3 J4: library part CMP-0074910-1, "Terminal Block, 5.08 mm, 2x1, Brass, TH", Color=Blue, Current_A=15A, Manufacturer="On-Shore Technology", Supplier Part Number 1=ED1609-ND, Voltage_V=300V
J5: library part CMP-0075484-1, "Header, 100mil, 3x1, Gold, TH", Manufacturer=Samtec, PartNumber=HTSW-103-07-G-S, Supplier Part Number 1=HTSW-103-07-G-S-ND
J6: library part CMP-0075412-2, "Header, 100mil, 6x2, Gold, TH", Color=Black, Current_A=6.3A, Manufacturer=Samtec, Supplier Part Number 1=SAM1028-06-ND, Voltage_V=550V
L1: library part CMP-0061054-1, "Inductor, Shielded, Composite, 550 nH, 29 A, 0.00142 ohm, SMD", Manufacturer=Coilcraft, Value1="0.00142 ohm", Value2=29A, ValueDisplayed=550nH
L2: library part CMP-0060183-1, "Inductor, Wirewound, Ceramic, 47 nH, 0.5 A, 0.31 ohm, SMD", Manufacturer=Coilcraft, PartNumber=0805CS-470XJLB, Supplier Part Number 1=994-0805CS-470XJLB, Value1="0.31 ohm", Value2=0.5A, ValueDisplayed=47nH
LBL1: library part CMP-0003625-1, "Thermal Transfer Printable Labels, 0.650\" W x 0.200\" H - 10,000 per roll", Manufacturer=Brady, Supplier Part Number 1=97C5133
Logo2: library part CMP-0074847-1, "FCC_disclaimer"
LOGO3: library part CMP-0074844-1
Logo4: library part CMP-0074769-1
LOGO5: library part CMP-0074837-1, "IEC 61010-1 Hot Surface Warning"
NT1: library part CMP-0078142-3, "Single point connection between nets.", Manufacturer=N/A
R1 R17: library part CMP-0016567-2, "RES, 0, 1%, 0.5 W, 1206", Manufacturer=Keystone, Power_W=500mW, Supplier Part Number 1=36-5108CT-ND, TempCo=ppm/C, Tolerance_%=1%, Value2=0.5W, Value_Code=0
R2 R7 R11: library part CMP-0023343-3, "RES, 0, 1%, 0.1 W, AEC-Q200 Grade 0, 0603", Manufacturer="Stackpole Electronics Inc", Power_W=100mW, Supplier Part Number 1=RMCF0603ZT0R00CT-ND, TempCo=ppm/C, Tolerance_%=1%, Value2=0.1W, Value_Code=0
R3 R12: library part CMP-0022324-4, "RES, 30.1 k, 1%, 0.1 W, AEC-Q200 Grade 0, 0603", Manufacturer=Vishay-Dale, Power_W=100mW, Supplier Part Number 1=541-30.1KHCT-ND, TempCo="100 ppm/C", Tolerance_%=1%, Value2=0.1W, Value_Code=30k1, ValueDisplayed=30.1k
R4: library part CMP-0023931-3, "RES, 20.0 k, 0.1%, 0.1 W, 0603", Manufacturer="Yageo America", Power_W=100mW, TempCo="25 ppm/C", Tolerance_%=0.1%, Value2=0.1W, Value_Code=20k0, ValueDisplayed=20.0k
R5: library part CMP-0022558-4, "RES, 6.04 k, 1%, 0.1 W, AEC-Q200 Grade 0, 0603", Manufacturer=Vishay-Dale, Power_W=100mW, Supplier Part Number 1=541-6.04KHCT-ND, TempCo="100 ppm/C", Tolerance_%=1%, Value2=0.1W, Value_Code=6k04, ValueDisplayed=6.04k
R6: library part CMP-0022098-4, "RES, 18.7 k, 1%, 0.1 W, AEC-Q200 Grade 0, 0603", Manufacturer=Vishay-Dale, Power_W=100mW, Supplier Part Number 1=541-18.7KHCT-ND, TempCo="100 ppm/C", Tolerance_%=1%, Value2=0.1W, Value_Code=18k7, ValueDisplayed=18.7k
R8: library part CMP-0022003-4, "RES, 10.0, 1%, 0.1 W, AEC-Q200 Grade 0, 0603", Manufacturer=Vishay-Dale, Power_W=100mW, Supplier Part Number 1=541-10.0HCT-ND, TempCo="100 ppm/C", Tolerance_%=1%, Value2=0.1W, Value_Code=10R0, ValueDisplayed=10.0
R9 R10: library part CMP-0021998-4, "RES, 10.0 k, 1%, 0.1 W, AEC-Q200 Grade 0, 0603", Manufacturer=Vishay-Dale, Power_W=100mW, Supplier Part Number 1=541-10.0KHCT-ND, TempCo="100 ppm/C", Tolerance_%=1%, Value2=0.1W, Value_Code=10k0, ValueDisplayed=10.0k
R13: library part CMP-0023212-5, "RES, 60.4 k, 1%, 0.1 W, 0603", Manufacturer=Yageo, Power_W=100mW, Supplier Part Number 1=311-60.4KHRCT-ND, TempCo="100 ppm/C", Tolerance_%=1%, Value2=0.1W, Value_Code=60k4, ValueDisplayed=60.4k
R14: library part CMP-0022770-4, "RES, 121 k, 1%, 0.1 W, 0603", Manufacturer=Yageo, Power_W=100mW, Supplier Part Number 1=311-121KHRCT-ND, TempCo="100 ppm/C", Tolerance_%=1%, Value2=0.1W, Value_Code=121k
R15: library part CMP-0022232-4, "RES, 243 k, 1%, 0.1 W, AEC-Q200 Grade 0, 0603", Manufacturer=Vishay-Dale, Power_W=100mW, Supplier Part Number 1=541-243KHCT-ND, TempCo="100 ppm/C", Tolerance_%=1%, Value2=0.1W, Value_Code=243k
R16: library part CMP-0018746-2, "RES, 2.2, 5%, 0.5 W, 1206", Manufacturer=Bourns, Power_W=500mW, Supplier Part Number 1=652-CRM1206JW2R2ELF, TempCo="100 ppm/C", Tolerance_%=5%, Value2=0.5W, Value_Code=2R20, ValueDisplayed=2.2
SH-J1 SH-J2: library part CMP-0003623-3, "Shunt, 100mil, Gold plated, Black", Alternate Manufacturer=3M, Alternate PartNumber=969102-0000-DA, Manufacturer=Samtec, Supplier Part Number 1=SAM8858-ND
TP1 TP3 TP13: library part CMP-0055147-1, "Test Point, Multipurpose, Red, TH", Color=Red, Manufacturer=Keystone, PartNumber=5010, Supplier Part Number 1=36-5010-ND
TP2 TP7 TP8 TP14: library part CMP-0055148-1, "Test Point, Multipurpose, Black, TH", Color=Black, Manufacturer=Keystone, PartNumber=5011, Supplier Part Number 1=36-5011-ND
TP4 TP5 TP6: library part CMP-0055146-1, "Test Point, Compact, Yellow, TH", Color=Yellow, Manufacturer=Keystone, PartNumber=5009, Supplier Part Number 1=36-5009-ND
TP9: library part CMP-0055145-1, "Test Point, Compact, Orange, TH", Color=Orange, Manufacturer=Keystone, PartNumber=5008, Supplier Part Number 1=36-5008-ND
TP10 TP11 TP12: library part CMP-0055150-1, "Test Point, Multipurpose, Orange, TH", Color=Orange, Manufacturer=Keystone, PartNumber=5013, Supplier Part Number 1=36-5013-ND
U1: library part CMP-0079178-4, "4-V to 16-V Input, 20-A Single Synchronous Step-Down Converter, RWW0021A (VQFN-HR-21)", Alternate Manufacturer="Texas Instruments", Alternate PartNumber=TPS54JB00RWWR, PartNumber=TPS54JB00RWWT
ZZ1: library part CMP-0003616-3
ZZ2: library part CMP-0077236-1
ZZ3: library part CMP-0077237-1
ZZ4: library part CMP-0077238-1

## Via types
v1: diameter 24, hole 12, Top Layer to Bottom Layer, tented both sides, 196 vias
v2: diameter 20, hole 10, Top Layer to Bottom Layer, tented both sides, 8 vias
v3: diameter 20, hole 8, Top Layer to Bottom Layer, tented both sides, 7 vias
v4: diameter 24, hole 10, Top Layer to Bottom Layer, tented both sides, 2 vias
v5: diameter 18, hole 8, Top Layer to Bottom Layer, tented both sides, 1 vias
v6: diameter 22, hole 12, Top Layer to Bottom Layer, tented both sides, 1 vias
